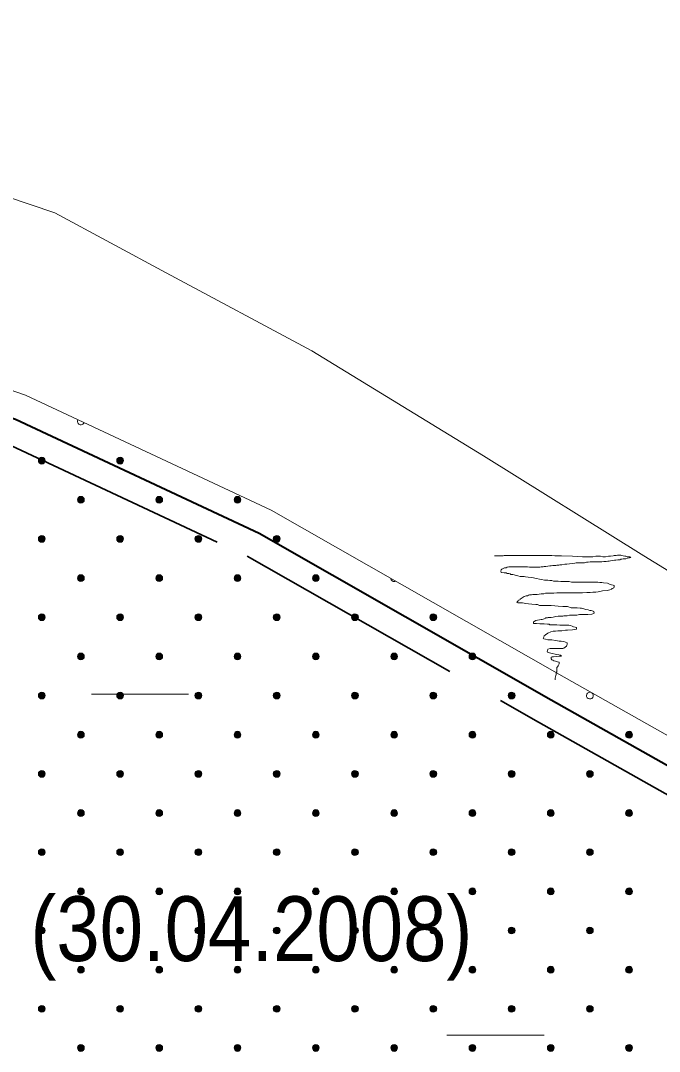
# Model space of a CAD drawing. Extents: x 640104 to 640970, y 6442278 to 6442689.
# Drawn here: x 640533.68 to 640553.41, y 6442346.2 to 6442378.03 of the extents above; entities that cross this region are included whole.
import ezdxf
from ezdxf.enums import TextEntityAlignment as Align

# ---------------------------------------------------------------- set-up
doc = ezdxf.new("R2010")
doc.units = 0
doc.header["$LTSCALE"] = 1.2
doc.linetypes.add('LONG_DASHED', pattern=[7.5, 6, -1.5])
for name, color, linetype, lineweight in [('31', 7, 'Continuous', 13), ('34', 7, 'Continuous', 25), ('35', 7, 'Continuous', 35), ('40', 7, 'Continuous', 13), ('45', 7, 'Continuous', 13), ('47', 7, 'Continuous', 13)]:
    doc.layers.add(name, color=color, linetype=linetype, lineweight=lineweight)

msp = doc.modelspace()

# ---------------------------------------------------------------- hatches: boundary and pattern name
at = {"layer": '45'}
for points in [[(640534.41, 6442364.517, 1), (640534.262, 6442364.369, 1)], [(640536.829, 6442364.517, 1), (640536.68, 6442364.369, 1)], [(640535.62, 6442363.308, 1), (640535.471, 6442363.16, 1)], [(640538.038, 6442363.308, 1), (640537.889, 6442363.16, 1)], [(640540.456, 6442363.308, 1), (640540.308, 6442363.16, 1)], [(640534.41, 6442362.099, 1), (640534.262, 6442361.951, 1)], [(640536.829, 6442362.099, 1), (640536.68, 6442361.951, 1)], [(640539.247, 6442362.099, 1), (640539.099, 6442361.951, 1)], [(640541.665, 6442362.099, 1), (640541.517, 6442361.951, 1)], [(640535.62, 6442360.89, 1), (640535.471, 6442360.741, 1)], [(640538.038, 6442360.89, 1), (640537.889, 6442360.741, 1)], [(640540.456, 6442360.89, 1), (640540.308, 6442360.741, 1)], [(640542.875, 6442360.89, 1), (640542.726, 6442360.741, 1)], [(640534.41, 6442359.681, 1), (640534.262, 6442359.532, 1)], [(640536.829, 6442359.681, 1), (640536.68, 6442359.532, 1)], [(640539.247, 6442359.681, 1), (640539.099, 6442359.532, 1)], [(640541.665, 6442359.681, 1), (640541.517, 6442359.532, 1)], [(640544.084, 6442359.681, 1), (640543.935, 6442359.532, 1)], [(640546.502, 6442359.681, 1), (640546.353, 6442359.532, 1)], [(640535.62, 6442358.472, 1), (640535.471, 6442358.323, 1)], [(640538.038, 6442358.472, 1), (640537.889, 6442358.323, 1)], [(640540.456, 6442358.472, 1), (640540.308, 6442358.323, 1)], [(640542.875, 6442358.472, 1), (640542.726, 6442358.323, 1)], [(640545.293, 6442358.472, 1), (640545.144, 6442358.323, 1)], [(640547.711, 6442358.472, 1), (640547.563, 6442358.323, 1)], [(640534.41, 6442357.263, 1), (640534.262, 6442357.114, 1)], [(640536.829, 6442357.263, 1), (640536.68, 6442357.114, 1)], [(640539.247, 6442357.263, 1), (640539.099, 6442357.114, 1)], [(640541.665, 6442357.263, 1), (640541.517, 6442357.114, 1)], [(640544.084, 6442357.263, 1), (640543.935, 6442357.114, 1)], [(640546.502, 6442357.263, 1), (640546.353, 6442357.114, 1)], [(640548.92, 6442357.263, 1), (640548.772, 6442357.114, 1)], [(640535.62, 6442356.053, 1), (640535.471, 6442355.905, 1)], [(640538.038, 6442356.053, 1), (640537.889, 6442355.905, 1)], [(640540.456, 6442356.053, 1), (640540.308, 6442355.905, 1)], [(640542.875, 6442356.053, 1), (640542.726, 6442355.905, 1)], [(640545.293, 6442356.053, 1), (640545.144, 6442355.905, 1)], [(640547.711, 6442356.053, 1), (640547.563, 6442355.905, 1)], [(640550.129, 6442356.053, 1), (640549.981, 6442355.905, 1)], [(640552.548, 6442356.053, 1), (640552.399, 6442355.905, 1)], [(640534.41, 6442354.844, 1), (640534.262, 6442354.696, 1)], [(640536.829, 6442354.844, 1), (640536.68, 6442354.696, 1)], [(640539.247, 6442354.844, 1), (640539.099, 6442354.696, 1)], [(640541.665, 6442354.844, 1), (640541.517, 6442354.696, 1)], [(640544.084, 6442354.844, 1), (640543.935, 6442354.696, 1)], [(640546.502, 6442354.844, 1), (640546.353, 6442354.696, 1)], [(640548.92, 6442354.844, 1), (640548.772, 6442354.696, 1)], [(640551.339, 6442354.844, 1), (640551.19, 6442354.696, 1)], [(640535.62, 6442353.635, 1), (640535.471, 6442353.487, 1)], [(640538.038, 6442353.635, 1), (640537.889, 6442353.487, 1)], [(640540.456, 6442353.635, 1), (640540.308, 6442353.487, 1)], [(640542.875, 6442353.635, 1), (640542.726, 6442353.487, 1)], [(640545.293, 6442353.635, 1), (640545.144, 6442353.487, 1)], [(640547.711, 6442353.635, 1), (640547.563, 6442353.487, 1)], [(640550.129, 6442353.635, 1), (640549.981, 6442353.487, 1)], [(640552.548, 6442353.635, 1), (640552.399, 6442353.487, 1)], [(640534.41, 6442352.426, 1), (640534.262, 6442352.277, 1)], [(640536.829, 6442352.426, 1), (640536.68, 6442352.277, 1)], [(640539.247, 6442352.426, 1), (640539.099, 6442352.277, 1)], [(640541.665, 6442352.426, 1), (640541.517, 6442352.277, 1)], [(640544.084, 6442352.426, 1), (640543.935, 6442352.277, 1)], [(640546.502, 6442352.426, 1), (640546.353, 6442352.277, 1)], [(640548.92, 6442352.426, 1), (640548.772, 6442352.277, 1)], [(640551.339, 6442352.426, 1), (640551.19, 6442352.277, 1)], [(640535.62, 6442351.217, 1), (640535.471, 6442351.068, 1)], [(640538.038, 6442351.217, 1), (640537.889, 6442351.068, 1)], [(640540.456, 6442351.217, 1), (640540.308, 6442351.068, 1)], [(640542.875, 6442351.217, 1), (640542.726, 6442351.068, 1)], [(640545.293, 6442351.217, 1), (640545.144, 6442351.068, 1)], [(640547.711, 6442351.217, 1), (640547.563, 6442351.068, 1)], [(640550.129, 6442351.217, 1), (640549.981, 6442351.068, 1)], [(640552.548, 6442351.217, 1), (640552.399, 6442351.068, 1)], [(640534.41, 6442350.008, 1), (640534.262, 6442349.859, 1)], [(640536.829, 6442350.008, 1), (640536.68, 6442349.859, 1)], [(640539.247, 6442350.008, 1), (640539.099, 6442349.859, 1)], [(640541.665, 6442350.008, 1), (640541.517, 6442349.859, 1)], [(640544.084, 6442350.008, 1), (640543.935, 6442349.859, 1)], [(640546.502, 6442350.008, 1), (640546.353, 6442349.859, 1)], [(640548.92, 6442350.008, 1), (640548.772, 6442349.859, 1)], [(640551.339, 6442350.008, 1), (640551.19, 6442349.859, 1)], [(640535.62, 6442348.798, 1), (640535.471, 6442348.65, 1)], [(640538.038, 6442348.798, 1), (640537.889, 6442348.65, 1)], [(640540.456, 6442348.798, 1), (640540.308, 6442348.65, 1)], [(640542.875, 6442348.798, 1), (640542.726, 6442348.65, 1)], [(640545.293, 6442348.798, 1), (640545.144, 6442348.65, 1)], [(640547.711, 6442348.798, 1), (640547.563, 6442348.65, 1)], [(640550.129, 6442348.798, 1), (640549.981, 6442348.65, 1)], [(640552.548, 6442348.798, 1), (640552.399, 6442348.65, 1)], [(640534.41, 6442347.589, 1), (640534.262, 6442347.441, 1)], [(640536.829, 6442347.589, 1), (640536.68, 6442347.441, 1)], [(640539.247, 6442347.589, 1), (640539.099, 6442347.441, 1)], [(640541.665, 6442347.589, 1), (640541.517, 6442347.441, 1)], [(640544.084, 6442347.589, 1), (640543.935, 6442347.441, 1)], [(640546.502, 6442347.589, 1), (640546.353, 6442347.441, 1)], [(640548.92, 6442347.589, 1), (640548.772, 6442347.441, 1)], [(640551.339, 6442347.589, 1), (640551.19, 6442347.441, 1)], [(640535.62, 6442346.38, 1), (640535.471, 6442346.232, 1)], [(640538.038, 6442346.38, 1), (640537.889, 6442346.232, 1)], [(640540.456, 6442346.38, 1), (640540.308, 6442346.232, 1)], [(640542.875, 6442346.38, 1), (640542.726, 6442346.232, 1)], [(640545.293, 6442346.38, 1), (640545.144, 6442346.232, 1)], [(640547.711, 6442346.38, 1), (640547.563, 6442346.232, 1)], [(640550.129, 6442346.38, 1), (640549.981, 6442346.232, 1)], [(640552.548, 6442346.38, 1), (640552.399, 6442346.232, 1)]]:
    msp.add_hatch(color=256, dxfattribs=at).paths.add_polyline_path(points)

# ---------------------------------------------------------------- linework, layer by layer
at = {"layer": '31'}
for points in [[(640473.18, 6442372.93), (640475.72, 6442371.27), (640478.28, 6442370.42), (640482.1, 6442370.17), (640486.83, 6442370.68), (640492.52, 6442372.22), (640499.75, 6442373.9), (640503.87, 6442374.64), (640508.34, 6442375.23), (640512.3, 6442375.38), (640519.42, 6442375.65), (640522.57, 6442375.3), (640526.38, 6442374.57), (640530.28, 6442373.6), (640534.74, 6442372.09), (640538.18, 6442370.24), (640542.68, 6442367.83), (640547.98, 6442364.59), (640552.93, 6442361.5)], [(640472.22, 6442370.64), (640475.92, 6442369.03), (640480.13, 6442368.11), (640486.56, 6442368.13), (640490.81, 6442368.83), (640497.84, 6442370.15), (640502.36, 6442371.12), (640509.6, 6442371.47), (640514.96, 6442371.33), (640519.35, 6442370.64), (640522.55, 6442370.08), (640525.96, 6442369.1), (640529.03, 6442368.13), (640533.83, 6442366.46), (640541.42, 6442362.91), (640550.47, 6442357.76), (640557.82, 6442353.61), (640561.26, 6442351.7), (640562.79, 6442350.94), (640563.97, 6442350.8), (640569.82, 6442350.38), (640578.08, 6442350.26)], [(640552.93, 6442361.5), (640555.56, 6442359.89), (640559, 6442357.85), (640560.54, 6442357.05), (640562.74, 6442356.09), (640564.12, 6442355.75), (640566.48, 6442355.59), (640571.69, 6442355.43), (640575.94, 6442355.51), (640578.08, 6442355.59)]]:
    msp.add_lwpolyline(points, dxfattribs=at)
at = {"layer": '35', "lineweight": 40}
msp.add_lwpolyline([(640461.31, 6442378.03), (640465.15, 6442374.93), (640468.48, 6442372.32), (640471.83, 6442369.94), (640475.67, 6442368.27), (640480.04, 6442367.31), (640486.63, 6442367.33), (640490.95, 6442368.04), (640498, 6442369.36), (640502.47, 6442370.33), (640509.61, 6442370.67), (640514.89, 6442370.53), (640519.22, 6442369.85), (640522.37, 6442369.3), (640525.73, 6442368.34), (640528.77, 6442367.37), (640533.53, 6442365.72), (640541.05, 6442362.2), (640550.07, 6442357.06), (640557.43, 6442352.91), (640560.88, 6442350.99), (640563.32, 6442349.78)], dxfattribs=at)
at = {"layer": '35', "linetype": 'LONG_DASHED'}
msp.add_lwpolyline([(640520.22, 6442368.86), (640522.19, 6442368.52), (640525.5, 6442367.57), (640528.52, 6442366.61), (640533.23, 6442364.98), (640540.68, 6442361.49), (640549.68, 6442356.37), (640557.03, 6442352.21), (640560.51, 6442350.29), (640562.52, 6442349.28)], dxfattribs=at)
at = {"layer": '40'}
for points in [[(640548.32, 6442361.5), (640548.38, 6442361.5), (640548.48, 6442361.5), (640548.59, 6442361.5), (640548.62, 6442361.51), (640548.72, 6442361.51), (640548.88, 6442361.51), (640549.2, 6442361.51), (640549.38, 6442361.51), (640549.42, 6442361.51), (640549.46, 6442361.51), (640549.53, 6442361.51), (640549.61, 6442361.51), (640549.72, 6442361.51), (640549.8, 6442361.51), (640549.86, 6442361.51), (640549.95, 6442361.51), (640550.02, 6442361.51), (640550.09, 6442361.51), (640550.18, 6442361.5), (640550.22, 6442361.5), (640550.3, 6442361.5), (640550.39, 6442361.5), (640550.73, 6442361.49), (640551.04, 6442361.47), (640551.14, 6442361.47), (640551.2, 6442361.47), (640551.23, 6442361.47), (640551.28, 6442361.47), (640551.35, 6442361.47), (640551.45, 6442361.49), (640551.5, 6442361.49), (640551.53, 6442361.49), (640551.56, 6442361.49), (640551.59, 6442361.49), (640551.66, 6442361.47), (640551.7, 6442361.47), (640551.75, 6442361.47), (640551.84, 6442361.49), (640551.9, 6442361.49), (640551.98, 6442361.5), (640552.01, 6442361.51), (640552.08, 6442361.51), (640552.12, 6442361.52), (640552.17, 6442361.52), (640552.22, 6442361.52), (640552.25, 6442361.51), (640552.29, 6442361.5), (640552.34, 6442361.49), (640552.37, 6442361.49)], [(640552.37, 6442361.49), (640552.42, 6442361.47), (640552.46, 6442361.47), (640552.5, 6442361.47), (640552.53, 6442361.45), (640552.5, 6442361.44), (640552.52, 6442361.45), (640552.48, 6442361.44), (640552.43, 6442361.43), (640552.37, 6442361.41), (640552.34, 6442361.41), (640552.29, 6442361.41), (640552.25, 6442361.4), (640552.22, 6442361.4), (640552.19, 6442361.38), (640552.13, 6442361.38), (640552.06, 6442361.37), (640552.02, 6442361.37), (640551.9, 6442361.35), (640551.86, 6442361.34), (640551.82, 6442361.34), (640551.77, 6442361.33), (640551.72, 6442361.33), (640551.69, 6442361.33), (640551.63, 6442361.32), (640551.59, 6442361.32), (640551.48, 6442361.32), (640551.42, 6442361.32), (640551.35, 6442361.32), (640551.27, 6442361.32), (640551.21, 6442361.31), (640551.16, 6442361.31), (640551.1, 6442361.29), (640551.04, 6442361.29), (640550.87, 6442361.29), (640550.84, 6442361.29), (640550.8, 6442361.28), (640550.73, 6442361.27), (640550.63, 6442361.26), (640550.55, 6442361.25), (640550.49, 6442361.25), (640550.4, 6442361.23), (640550.34, 6442361.23), (640550.3, 6442361.21), (640550.24, 6442361.21), (640550.21, 6442361.2), (640550.18, 6442361.2), (640550.12, 6442361.2), (640550.07, 6442361.19), (640550.03, 6442361.19), (640549.9, 6442361.17), (640549.85, 6442361.17)], [(640549.85, 6442361.17), (640549.82, 6442361.16), (640549.76, 6442361.16), (640549.72, 6442361.15), (640549.68, 6442361.15), (640549.65, 6442361.15), (640549.6, 6442361.15), (640549.55, 6442361.15), (640549.5, 6442361.15), (640549.43, 6442361.15), (640549.4, 6442361.15), (640549.34, 6442361.16), (640549.3, 6442361.16), (640549.26, 6442361.16), (640549.23, 6442361.16), (640549.18, 6442361.16), (640549.13, 6442361.16), (640549.06, 6442361.16), (640549.02, 6442361.16), (640548.99, 6442361.16), (640548.93, 6442361.16), (640548.89, 6442361.16), (640548.84, 6442361.16), (640548.81, 6442361.16), (640548.76, 6442361.16), (640548.71, 6442361.15), (640548.68, 6442361.13), (640548.63, 6442361.13), (640548.59, 6442361.11), (640548.57, 6442361.1), (640548.54, 6442361.09), (640548.52, 6442361.07), (640548.51, 6442361.03), (640548.52, 6442360.99), (640548.62, 6442360.98), (640548.68, 6442360.98), (640548.71, 6442360.96), (640548.76, 6442360.96), (640548.8, 6442360.95), (640548.82, 6442360.93), (640548.88, 6442360.93), (640548.93, 6442360.92), (640548.96, 6442360.91), (640549.04, 6442360.89), (640549.11, 6442360.87), (640549.18, 6442360.87), (640549.23, 6442360.86), (640549.28, 6442360.85), (640549.36, 6442360.84), (640549.47, 6442360.83)], [(640549.47, 6442360.83), (640549.61, 6442360.8), (640549.71, 6442360.78), (640549.77, 6442360.77), (640549.86, 6442360.75), (640549.96, 6442360.75), (640550.03, 6442360.74), (640550.09, 6442360.74), (640550.14, 6442360.72), (640550.22, 6442360.72), (640550.28, 6442360.72), (640550.37, 6442360.71), (640550.45, 6442360.71), (640550.52, 6442360.71), (640550.62, 6442360.71), (640550.7, 6442360.69), (640550.76, 6442360.69), (640550.8, 6442360.69), (640550.87, 6442360.69), (640550.94, 6442360.69), (640551.03, 6442360.69), (640551.12, 6442360.69), (640551.21, 6442360.69), (640551.27, 6442360.69), (640551.35, 6442360.69), (640551.39, 6442360.69), (640551.45, 6442360.69), (640551.51, 6442360.69), (640551.57, 6442360.68), (640551.63, 6442360.68), (640551.68, 6442360.67), (640551.81, 6442360.66), (640551.87, 6442360.63), (640551.93, 6442360.61), (640551.98, 6442360.6), (640552.01, 6442360.59), (640552.01, 6442360.55), (640552, 6442360.51), (640551.98, 6442360.5), (640551.95, 6442360.49), (640551.93, 6442360.47), (640551.88, 6442360.45), (640551.8, 6442360.43), (640551.65, 6442360.42), (640551.52, 6442360.39), (640551.45, 6442360.38), (640551.35, 6442360.38), (640551.27, 6442360.37), (640551.17, 6442360.37), (640551.04, 6442360.36), (640550.85, 6442360.36), (640550.68, 6442360.36)], [(640550.68, 6442360.36), (640550.6, 6442360.36), (640550.52, 6442360.36), (640550.44, 6442360.36), (640550.38, 6442360.36), (640550.32, 6442360.36), (640550.24, 6442360.36), (640550.15, 6442360.35), (640549.97, 6442360.35), (640549.89, 6442360.35), (640549.84, 6442360.33), (640549.76, 6442360.33), (640549.64, 6442360.31), (640549.5, 6442360.31), (640549.46, 6442360.3), (640549.4, 6442360.3), (640549.37, 6442360.29), (640549.34, 6442360.27), (640549.3, 6442360.27), (640549.26, 6442360.26), (640549.23, 6442360.25), (640549.2, 6442360.23), (640549.14, 6442360.19), (640549.11, 6442360.17), (640549.1, 6442360.14), (640549.06, 6442360.13), (640549.05, 6442360.11), (640549.02, 6442360.08), (640549.01, 6442360.06), (640549.04, 6442360.05), (640549.07, 6442360.05), (640549.13, 6442360.05), (640549.18, 6442360.05), (640549.29, 6442360.03), (640549.37, 6442360.02), (640549.47, 6442360.01), (640549.59, 6442360), (640549.65, 6442360), (640549.71, 6442359.97), (640549.77, 6442359.97), (640549.94, 6442359.97), (640550.07, 6442359.97), (640550.18, 6442359.96), (640550.28, 6442359.95), (640550.43, 6442359.94), (640550.57, 6442359.94), (640550.69, 6442359.9), (640550.78, 6442359.9), (640550.87, 6442359.9), (640550.96, 6442359.89)], [(640550.96, 6442359.89), (640551, 6442359.89), (640551.05, 6442359.88), (640551.14, 6442359.85), (640551.21, 6442359.84), (640551.26, 6442359.82), (640551.3, 6442359.81), (640551.36, 6442359.79), (640551.39, 6442359.78), (640551.4, 6442359.73), (640551.38, 6442359.72), (640551.35, 6442359.71), (640551.32, 6442359.7), (640551.2, 6442359.69), (640551.14, 6442359.69), (640551.1, 6442359.69), (640551.03, 6442359.69), (640550.94, 6442359.69), (640550.86, 6442359.67), (640550.81, 6442359.67), (640550.76, 6442359.67), (640550.63, 6442359.67), (640550.56, 6442359.65), (640550.52, 6442359.65), (640550.46, 6442359.65), (640550.43, 6442359.64), (640550.37, 6442359.64), (640550.28, 6442359.64), (640550.21, 6442359.63), (640550.13, 6442359.61), (640550.07, 6442359.6), (640550.03, 6442359.6), (640549.98, 6442359.6), (640549.95, 6442359.59), (640549.89, 6442359.59), (640549.88, 6442359.57), (640549.82, 6442359.55), (640549.79, 6442359.54), (640549.76, 6442359.54), (640549.71, 6442359.53), (640549.65, 6442359.52), (640549.59, 6442359.51), (640549.54, 6442359.48), (640549.52, 6442359.46), (640549.52, 6442359.41), (640549.55, 6442359.41), (640549.62, 6442359.41), (640549.72, 6442359.4), (640549.8, 6442359.4), (640549.85, 6442359.4), (640549.95, 6442359.39), (640550.01, 6442359.39)], [(640550.01, 6442359.39), (640550.03, 6442359.37), (640550.07, 6442359.37), (640550.13, 6442359.37), (640550.2, 6442359.37), (640550.24, 6442359.37), (640550.34, 6442359.36), (640550.43, 6442359.36), (640550.46, 6442359.36), (640550.51, 6442359.36), (640550.55, 6442359.36), (640550.61, 6442359.36), (640550.67, 6442359.35), (640550.72, 6442359.33), (640550.76, 6442359.31), (640550.81, 6442359.3), (640550.85, 6442359.29), (640550.85, 6442359.24), (640550.73, 6442359.22), (640550.57, 6442359.21), (640550.51, 6442359.21), (640550.4, 6442359.19), (640550.34, 6442359.19), (640550.27, 6442359.19), (640550.2, 6442359.18), (640550.13, 6442359.18), (640550.06, 6442359.16), (640549.97, 6442359.12), (640549.95, 6442359.1), (640549.9, 6442359.07), (640549.88, 6442359.05), (640549.85, 6442359.03), (640549.84, 6442358.99), (640549.82, 6442358.95), (640549.84, 6442358.94), (640549.89, 6442358.93), (640549.96, 6442358.91), (640550.09, 6442358.91), (640550.2, 6442358.89), (640550.26, 6442358.88), (640550.31, 6442358.87), (640550.38, 6442358.87), (640550.46, 6442358.86), (640550.56, 6442358.82), (640550.56, 6442358.77), (640550.55, 6442358.74), (640550.54, 6442358.71), (640550.46, 6442358.65), (640550.43, 6442358.64), (640550.37, 6442358.64), (640550.28, 6442358.64), (640550.2, 6442358.64), (640550.13, 6442358.64), (640550.04, 6442358.64), (640549.96, 6442358.62), (640549.95, 6442358.58), (640549.94, 6442358.56), (640549.95, 6442358.53), (640549.98, 6442358.52), (640550.1, 6442358.49), (640550.19, 6442358.47), (640550.24, 6442358.46), (640550.3, 6442358.45), (640550.36, 6442358.44), (640550.39, 6442358.41), (640550.37, 6442358.4), (640550.31, 6442358.4), (640550.24, 6442358.39), (640550.14, 6442358.38), (640550.1, 6442358.38), (640550.07, 6442358.37), (640550.07, 6442358.32), (640550.09, 6442358.29), (640550.12, 6442358.28), (640550.15, 6442358.26), (640550.2, 6442358.25), (640550.26, 6442358.23), (640550.31, 6442358.22), (640550.32, 6442358.17), (640550.3, 6442358.15), (640550.28, 6442358.11), (640550.26, 6442358.08), (640550.24, 6442358.05), (640550.24, 6442358.01), (640550.24, 6442357.96), (640550.24, 6442357.92), (640550.22, 6442357.89), (640550.22, 6442357.84), (640550.21, 6442357.81), (640550.2, 6442357.77), (640550.19, 6442357.73), (640550.19, 6442357.68), (640550.19, 6442357.67), (640550.19, 6442357.71)]]:
    msp.add_lwpolyline(points, dxfattribs=at)
at = {"layer": '45'}
for centre in [(640534.336, 6442364.443), (640536.755, 6442364.443), (640535.545, 6442363.234), (640537.964, 6442363.234), (640540.382, 6442363.234), (640534.336, 6442362.025), (640536.755, 6442362.025), (640539.173, 6442362.025), (640541.591, 6442362.025), (640535.545, 6442360.816), (640537.964, 6442360.816), (640540.382, 6442360.816), (640542.8, 6442360.816), (640534.336, 6442359.607), (640536.755, 6442359.607), (640539.173, 6442359.607), (640541.591, 6442359.607), (640544.009, 6442359.607), (640546.428, 6442359.607), (640535.545, 6442358.397), (640537.964, 6442358.397), (640540.382, 6442358.397), (640542.8, 6442358.397), (640545.219, 6442358.397), (640547.637, 6442358.397), (640534.336, 6442357.188), (640536.755, 6442357.188), (640539.173, 6442357.188), (640541.591, 6442357.188), (640544.009, 6442357.188), (640546.428, 6442357.188), (640548.846, 6442357.188), (640535.545, 6442355.979), (640537.964, 6442355.979), (640540.382, 6442355.979), (640542.8, 6442355.979), (640545.219, 6442355.979), (640547.637, 6442355.979), (640550.055, 6442355.979), (640552.473, 6442355.979), (640534.336, 6442354.77), (640536.755, 6442354.77), (640539.173, 6442354.77), (640541.591, 6442354.77), (640544.009, 6442354.77), (640546.428, 6442354.77), (640548.846, 6442354.77), (640551.264, 6442354.77), (640535.545, 6442353.561), (640537.964, 6442353.561), (640540.382, 6442353.561), (640542.8, 6442353.561), (640545.219, 6442353.561), (640547.637, 6442353.561), (640550.055, 6442353.561), (640552.473, 6442353.561), (640534.336, 6442352.352), (640536.755, 6442352.352), (640539.173, 6442352.352), (640541.591, 6442352.352), (640544.009, 6442352.352), (640546.428, 6442352.352), (640548.846, 6442352.352), (640551.264, 6442352.352), (640535.545, 6442351.142), (640537.964, 6442351.142), (640540.382, 6442351.142), (640542.8, 6442351.142), (640545.219, 6442351.142), (640547.637, 6442351.142), (640550.055, 6442351.142), (640552.473, 6442351.142), (640534.336, 6442349.933), (640536.755, 6442349.933), (640539.173, 6442349.933), (640541.591, 6442349.933), (640544.009, 6442349.933), (640546.428, 6442349.933), (640548.846, 6442349.933), (640551.264, 6442349.933), (640535.545, 6442348.724), (640537.964, 6442348.724), (640540.382, 6442348.724), (640542.8, 6442348.724), (640545.219, 6442348.724), (640547.637, 6442348.724), (640550.055, 6442348.724), (640552.473, 6442348.724), (640534.336, 6442347.515), (640536.755, 6442347.515), (640539.173, 6442347.515), (640541.591, 6442347.515), (640544.009, 6442347.515), (640546.428, 6442347.515), (640548.846, 6442347.515), (640551.264, 6442347.515), (640535.545, 6442346.306), (640537.964, 6442346.306), (640540.382, 6442346.306), (640542.8, 6442346.306), (640545.219, 6442346.306), (640547.637, 6442346.306), (640550.055, 6442346.306), (640552.473, 6442346.306)]:
    msp.add_circle(centre, 0.105, dxfattribs=at)
for centre, start, end in [((640535.545, 6442365.652), 152.8483, 337.0029), ((640545.219, 6442360.816), 186.0097, 294.6905), ((640551.264, 6442357.188), 68.0041, 53.1267)]:
    msp.add_arc(centre, 0.105, start, end, dxfattribs=at)
at = {"layer": '47'}
for p, q in [((640535.87, 6442357.23), (640538.87, 6442357.23)), ((640546.85, 6442346.7), (640549.85, 6442346.7))]:
    msp.add_line(p, q, dxfattribs=at)

# ---------------------------------------------------------------- texts
at = {"layer": '34', "width": 0.9}
msp.add_text('(30.04.2008)', height=2, dxfattribs=at).set_placement((640540.81, 6442348.99), align=Align.CENTER)

doc.saveas('drawing.dxf')
